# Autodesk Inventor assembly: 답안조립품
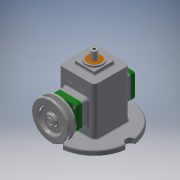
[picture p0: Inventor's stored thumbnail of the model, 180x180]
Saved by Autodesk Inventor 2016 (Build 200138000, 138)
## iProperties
Created: 2018-07
Part Number: 답안조립품
Document SubType Name: Assembly
Designer: 2-PC11
Author: 2-PC11
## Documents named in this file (16)
- C:\Users\2-PC11\Desktop\갈매기\480708V1014\답안조립품.iam
- C:\Users\2-PC11\Desktop\갈매기\480708V1014\본체.ipt
- C:\Users\2-PC11\Desktop\갈매기\480708V1014\앞커버.ipt
- C:\Users\2-PC11\Desktop\갈매기\480708V1014\뒤커버.ipt
- C:\Users\2-PC11\Desktop\갈매기\480708V1014\편심축.ipt
- C:\Users\2-PC11\Desktop\갈매기\480708V1014\베어링 12x32x10.ipt
- C:\Users\2-PC11\Desktop\갈매기\480708V1014\오일 실 12 25 7.ipt
- C:\Users\2-PC11\Desktop\갈매기\480708V1014\링크.ipt
- C:\Users\2-PC11\Desktop\갈매기\480708V1014\슬라이드.ipt
- C:\Users\2-PC11\Desktop\갈매기\480708V1014\핀 5x18.ipt
- C:\Users\2-PC11\Desktop\갈매기\480708V1014\고정핀 1.2x8.ipt
- C:\Users\2-PC11\Desktop\갈매기\480708V1014\부시.ipt
- C:\Users\2-PC11\Desktop\갈매기\480708V1014\볼트 M4.ipt
- C:\Users\2-PC11\Desktop\갈매기\480708V1014\V벨트풀리.ipt
- C:\Users\2-PC11\Desktop\갈매기\480708V1014\멈춤나사 M3x8.ipt
- C:\Users\2-PC11\Desktop\갈매기\480708V1014\키 4x4x10.ipt
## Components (3 placed, 3 different names)
1. 핀 5x18:1
2. 고정핀 1.2x8:1
3. V벨트풀리:1
